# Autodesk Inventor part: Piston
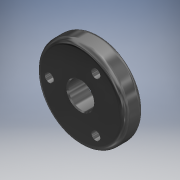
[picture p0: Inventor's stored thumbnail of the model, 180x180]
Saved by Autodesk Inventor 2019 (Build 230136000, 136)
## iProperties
Shininess: 50.0
Compacted: True
Length Units: 11272
Angle Units: 11279
Time Units: 11290
Mass Units: 11286
Length Display Precision: 4
Angle Display Precision: 2
Company: Autodesk
Created: 2000-03
Part Number: Piston
Project: Inventor Samples
User Status: IN PROGRESS
Document SubType Name: Modeling
Designer: Autodesk, Inc.
Density: 0.93 g/cm^3
Mass: 0.178192 g
Surface Area: 2.75391 cm^2
Volume: 0.191604 cm^3
Material: Rubber
Appearance: Rubber - Black - Version 1.1
Density: 0.0
Volumn: 0.0
Area: 0.0
PropertySet Name: Model Information
Control State: 0
Master: False
Checked Out: False
Checked Out Date: 2018-05-30
Last Check In Date: 2018-05-30
Author: Autodesk, Inc.
Revision Number: A
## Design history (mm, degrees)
node "Extrusion1" dims "d2" = 2.38125, "d3" = 0
  sketch "Sketch2"
    geometry: C1 r 5.461 at (-8.672, -9.008); C2 r 1.587 at (-8.672, -9.008)
    constraints: 2 centre point, 1 coincident
    dimensions: "d0" = 3.175 diameter of C2; "d1" = 10.922 diameter of C1
node "Fillet1" dims "d4" = 0.635
node "Chamfer1" dims "d5" = 0.127, "d6" = 0.127, "d14" = 45 deg
node "Extrusion2" dims "d9" = 2.38125, "d10" = 0
  sketch "Sketch3"
    geometry: C1 r 4.826 at (0, 0) reference; C2 r 0.546 at (-3.81, 0)
    constraints: 1 centre point, 1 horizontal alignment
    dimensions: "d7" = 1.0922 diameter of C2; "d8" = 3.81 distance of C1.centre C2.centre
node "Circular Pattern1" dims "d11" = 30, "d13" = 120 deg
body "Solid1"
